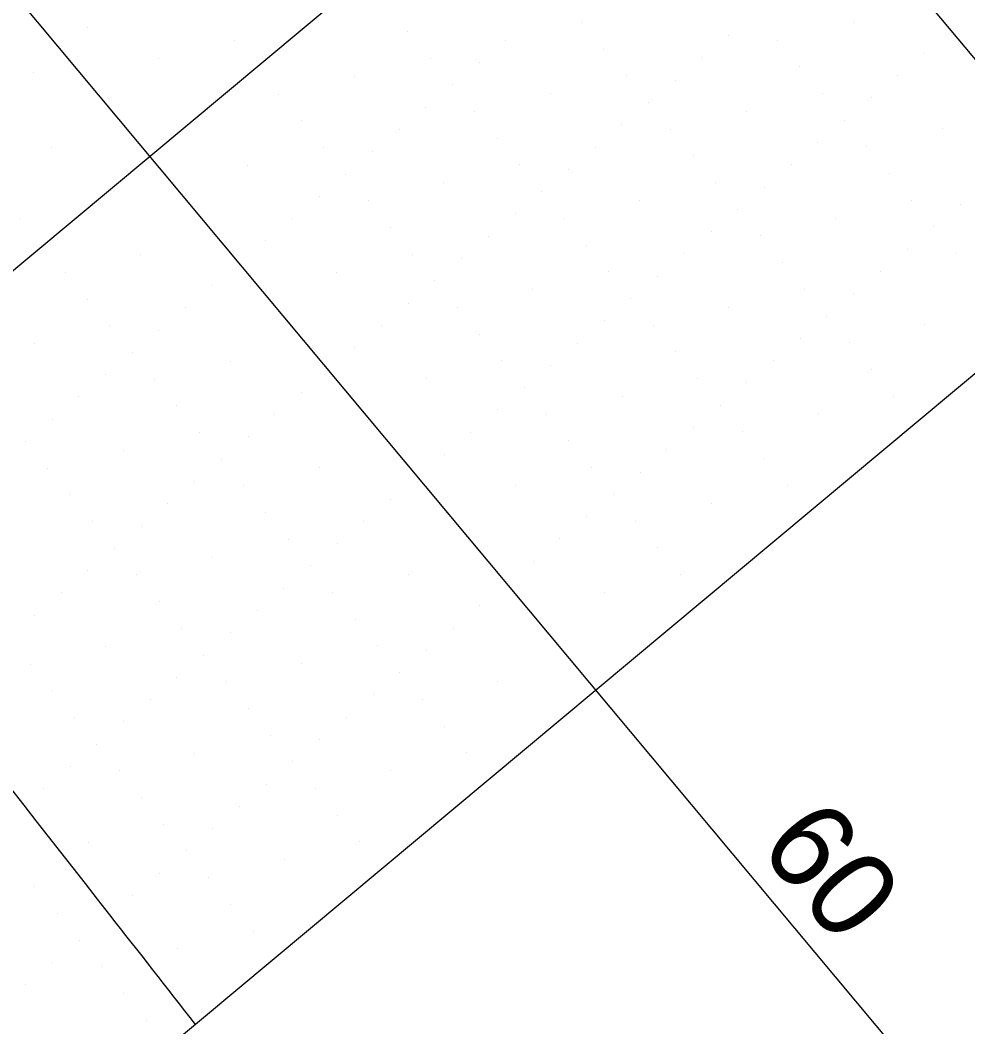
# Model space of a CAD drawing. Extents: x 2042995 to 2043795, y 305365 to 306249.
# Drawn here: x 2043542.18 to 2043569.43, y 305524.47 to 305553.43 of the extents above; entities that cross this region are included whole.
import ezdxf

# ---------------------------------------------------------------- set-up
doc = ezdxf.new("R2010")
doc.units = 0
for name, color, linetype in [('BR_BORDER LINES', 7, 'Continuous'), ('BR_CONCRETE', 7, 'Continuous'), ('BR_GRID DOTS', 7, 'Continuous'), ('BR_GRID LINES', 7, 'Continuous'), ('BR_TEXT', 7, 'Continuous')]:
    doc.layers.add(name, color=color, linetype=linetype)

msp = doc.modelspace()

# ---------------------------------------------------------------- linework, layer by layer
at = {"layer": 'BR_BORDER LINES'}
msp.add_line((2043604.779, 305572.617), (2043493.489, 305479.668), dxfattribs=at)
at = {"layer": 'BR_CONCRETE'}
msp.add_spline([(2043139.109, 306017.548), (2043148.199, 306007.16), (2043160.233, 305993.368), (2043172.245, 305979.557), (2043184.234, 305965.727), (2043196.201, 305951.879), (2043208.145, 305938.012), (2043220.067, 305924.126), (2043231.966, 305910.221), (2043243.843, 305896.297), (2043255.698, 305882.355), (2043267.529, 305868.394), (2043279.339, 305854.414), (2043291.126, 305840.415), (2043302.89, 305826.398), (2043314.632, 305812.361), (2043326.352, 305798.306), (2043338.049, 305784.233), (2043349.724, 305770.14), (2043361.376, 305756.029), (2043373.005, 305741.899), (2043384.613, 305727.75), (2043396.197, 305713.582), (2043407.76, 305699.396), (2043419.299, 305685.191), (2043430.817, 305670.967), (2043442.311, 305656.724), (2043453.784, 305642.463), (2043465.234, 305628.182), (2043476.661, 305613.883), (2043488.066, 305599.566), (2043499.448, 305585.229), (2043510.808, 305570.874), (2043522.146, 305556.5), (2043533.461, 305542.107), (2043544.753, 305527.695), (2043547.219, 305524.543)], degree=3, dxfattribs=at)
at = {"layer": 'BR_GRID DOTS'}
for p, q in [((2043558.323, 305553.361), (2043558.323, 305553.361)), ((2043566.133, 305553.369), (2043566.133, 305553.369)), ((2043544.111, 305553.217), (2043544.111, 305553.217)), ((2043553.33, 305553.099), (2043553.33, 305553.099)), ((2043568.95, 305553.116), (2043568.95, 305553.116)), ((2043548.337, 305552.838), (2043548.337, 305552.838)), ((2043556.147, 305552.846), (2043556.147, 305552.846)), ((2043562.549, 305552.981), (2043562.549, 305552.981)), ((2043563.957, 305552.855), (2043563.957, 305552.855)), ((2043543.344, 305552.576), (2043543.344, 305552.576)), ((2043558.964, 305552.593), (2043558.964, 305552.593)), ((2043568.183, 305552.475), (2043568.183, 305552.475)), ((2043546.161, 305552.323), (2043546.161, 305552.323)), ((2043553.971, 305552.332), (2043553.971, 305552.332)), ((2043555.379, 305552.205), (2043555.379, 305552.205)), ((2043561.781, 305552.34), (2043561.781, 305552.34)), ((2043542.576, 305551.935), (2043542.576, 305551.935)), ((2043564.598, 305552.087), (2043564.598, 305552.087)), ((2043551.795, 305551.817), (2043551.795, 305551.817)), ((2043559.605, 305551.826), (2043559.605, 305551.826)), ((2043561.014, 305551.699), (2043561.014, 305551.699)), ((2043567.415, 305551.834), (2043567.415, 305551.834)), ((2043554.612, 305551.564), (2043554.612, 305551.564)), ((2043565.239, 305551.32), (2043565.239, 305551.32)), ((2043549.619, 305551.303), (2043549.619, 305551.303)), ((2043557.429, 305551.311), (2043557.429, 305551.311)), ((2043560.246, 305551.058), (2043560.246, 305551.058)), ((2043566.648, 305551.193), (2043566.648, 305551.193)), ((2043553.844, 305550.923), (2043553.844, 305550.923)), ((2043555.253, 305550.797), (2043555.253, 305550.797)), ((2043563.063, 305550.805), (2043563.063, 305550.805)), ((2043550.26, 305550.535), (2043550.26, 305550.535)), ((2043565.88, 305550.552), (2043565.88, 305550.552)), ((2043553.077, 305550.282), (2043553.077, 305550.282)), ((2043559.479, 305550.417), (2043559.479, 305550.417)), ((2043560.887, 305550.291), (2043560.887, 305550.291)), ((2043568.697, 305550.299), (2043568.697, 305550.299)), ((2043555.894, 305550.029), (2043555.894, 305550.029)), ((2043565.113, 305549.911), (2043565.113, 305549.911)), ((2043543.091, 305549.759), (2043543.091, 305549.759)), ((2043550.901, 305549.768), (2043550.901, 305549.768)), ((2043552.309, 305549.641), (2043552.309, 305549.641)), ((2043558.711, 305549.776), (2043558.711, 305549.776)), ((2043566.521, 305549.785), (2043566.521, 305549.785)), ((2043561.528, 305549.523), (2043561.528, 305549.523)), ((2043548.725, 305549.253), (2043548.725, 305549.253)), ((2043551.542, 305549), (2043551.542, 305549)), ((2043556.535, 305549.262), (2043556.535, 305549.262)), ((2043557.944, 305549.135), (2043557.944, 305549.135)), ((2043564.345, 305549.27), (2043564.345, 305549.27)), ((2043567.162, 305549.017), (2043567.162, 305549.017)), ((2043554.359, 305548.747), (2043554.359, 305548.747)), ((2043562.169, 305548.756), (2043562.169, 305548.756)), ((2043557.176, 305548.494), (2043557.176, 305548.494)), ((2043563.578, 305548.629), (2043563.578, 305548.629)), ((2043550.774, 305548.359), (2043550.774, 305548.359)), ((2043552.183, 305548.232), (2043552.183, 305548.232)), ((2043559.993, 305548.241), (2043559.993, 305548.241)), ((2043567.803, 305548.25), (2043567.803, 305548.25)), ((2043556.409, 305547.853), (2043556.409, 305547.853)), ((2043562.81, 305547.988), (2043562.81, 305547.988)), ((2043569.212, 305548.123), (2043569.212, 305548.123)), ((2043542.197, 305547.709), (2043542.197, 305547.709)), ((2043550.007, 305547.718), (2043550.007, 305547.718)), ((2043557.817, 305547.727), (2043557.817, 305547.727)), ((2043565.627, 305547.735), (2043565.627, 305547.735)), ((2043552.824, 305547.465), (2043552.824, 305547.465)), ((2043562.043, 305547.347), (2043562.043, 305547.347)), ((2043568.444, 305547.482), (2043568.444, 305547.482)), ((2043549.239, 305547.077), (2043549.239, 305547.077)), ((2043555.641, 305547.212), (2043555.641, 305547.212)), ((2043563.451, 305547.221), (2043563.451, 305547.221)), ((2043545.655, 305546.689), (2043545.655, 305546.689)), ((2043553.465, 305546.697), (2043553.465, 305546.697)), ((2043558.458, 305546.959), (2043558.458, 305546.959)), ((2043561.275, 305546.706), (2043561.275, 305546.706)), ((2043567.677, 305546.841), (2043567.677, 305546.841)), ((2043569.085, 305546.715), (2043569.085, 305546.715)), ((2043548.472, 305546.436), (2043548.472, 305546.436)), ((2043554.874, 305546.571), (2043554.874, 305546.571)), ((2043564.092, 305546.453), (2043564.092, 305546.453)), ((2043543.479, 305546.174), (2043543.479, 305546.174)), ((2043551.289, 305546.183), (2043551.289, 305546.183)), ((2043559.099, 305546.191), (2043559.099, 305546.191)), ((2043566.909, 305546.2), (2043566.909, 305546.2)), ((2043554.106, 305545.93), (2043554.106, 305545.93)), ((2043560.508, 305546.065), (2043560.508, 305546.065)), ((2043547.704, 305545.795), (2043547.704, 305545.795)), ((2043556.923, 305545.677), (2043556.923, 305545.677)), ((2043564.733, 305545.686), (2043564.733, 305545.686)), ((2043566.142, 305545.559), (2043566.142, 305545.559)), ((2043544.12, 305545.407), (2043544.12, 305545.407)), ((2043553.338, 305545.289), (2043553.338, 305545.289)), ((2043559.74, 305545.424), (2043559.74, 305545.424)), ((2043546.937, 305545.154), (2043546.937, 305545.154)), ((2043554.747, 305545.162), (2043554.747, 305545.162)), ((2043562.557, 305545.171), (2043562.557, 305545.171)), ((2043558.973, 305544.783), (2043558.973, 305544.783)), ((2043560.381, 305544.656), (2043560.381, 305544.656)), ((2043565.374, 305544.918), (2043565.374, 305544.918)), ((2043568.191, 305544.665), (2043568.191, 305544.665)), ((2043544.761, 305544.639), (2043544.761, 305544.639)), ((2043546.169, 305544.513), (2043546.169, 305544.513)), ((2043552.571, 305544.648), (2043552.571, 305544.648)), ((2043555.388, 305544.395), (2043555.388, 305544.395)), ((2043542.585, 305544.125), (2043542.585, 305544.125)), ((2043558.205, 305544.142), (2043558.205, 305544.142)), ((2043564.607, 305544.277), (2043564.607, 305544.277)), ((2043566.015, 305544.15), (2043566.015, 305544.15)), ((2043545.402, 305543.872), (2043545.402, 305543.872)), ((2043551.803, 305544.007), (2043551.803, 305544.007)), ((2043561.022, 305543.889), (2043561.022, 305543.889)), ((2043548.219, 305543.619), (2043548.219, 305543.619)), ((2043556.029, 305543.627), (2043556.029, 305543.627)), ((2043557.438, 305543.501), (2043557.438, 305543.501)), ((2043563.839, 305543.636), (2043563.839, 305543.636)), ((2043544.634, 305543.231), (2043544.634, 305543.231)), ((2043551.036, 305543.366), (2043551.036, 305543.366)), ((2043566.656, 305543.383), (2043566.656, 305543.383)), ((2043546.043, 305543.104), (2043546.043, 305543.104)), ((2043553.853, 305543.113), (2043553.853, 305543.113)), ((2043561.663, 305543.121), (2043561.663, 305543.121)), ((2043563.072, 305542.995), (2043563.072, 305542.995)), ((2043550.268, 305542.725), (2043550.268, 305542.725)), ((2043556.67, 305542.86), (2043556.67, 305542.86)), ((2043543.867, 305542.59), (2043543.867, 305542.59)), ((2043559.487, 305542.607), (2043559.487, 305542.607)), ((2043562.304, 305542.354), (2043562.304, 305542.354)), ((2043567.297, 305542.615), (2043567.297, 305542.615)), ((2043546.684, 305542.337), (2043546.684, 305542.337)), ((2043549.501, 305542.084), (2043549.501, 305542.084)), ((2043555.903, 305542.219), (2043555.903, 305542.219)), ((2043557.311, 305542.092), (2043557.311, 305542.092)), ((2043565.121, 305542.101), (2043565.121, 305542.101)), ((2043543.099, 305541.949), (2043543.099, 305541.949)), ((2043547.325, 305541.569), (2043547.325, 305541.569)), ((2043555.135, 305541.578), (2043555.135, 305541.578)), ((2043561.537, 305541.713), (2043561.537, 305541.713)), ((2043562.945, 305541.586), (2043562.945, 305541.586)), ((2043542.332, 305541.308), (2043542.332, 305541.308)), ((2043548.733, 305541.443), (2043548.733, 305541.443)), ((2043557.952, 305541.325), (2043557.952, 305541.325)), ((2043545.149, 305541.055), (2043545.149, 305541.055)), ((2043554.368, 305540.937), (2043554.368, 305540.937)), ((2043560.769, 305541.072), (2043560.769, 305541.072)), ((2043547.966, 305540.802), (2043547.966, 305540.802)), ((2043563.586, 305540.819), (2043563.586, 305540.819)), ((2043542.973, 305540.54), (2043542.973, 305540.54)), ((2043550.783, 305540.549), (2043550.783, 305540.549)), ((2043558.593, 305540.557), (2043558.593, 305540.557)), ((2043560.002, 305540.431), (2043560.002, 305540.431)), ((2043547.198, 305540.161), (2043547.198, 305540.161)), ((2043548.607, 305540.034), (2043548.607, 305540.034)), ((2043553.6, 305540.296), (2043553.6, 305540.296)), ((2043556.417, 305540.043), (2043556.417, 305540.043)), ((2043564.227, 305540.051), (2043564.227, 305540.051)), ((2043543.614, 305539.773), (2043543.614, 305539.773)), ((2043559.234, 305539.79), (2043559.234, 305539.79)), ((2043546.431, 305539.52), (2043546.431, 305539.52)), ((2043552.833, 305539.655), (2043552.833, 305539.655)), ((2043562.051, 305539.537), (2043562.051, 305539.537)), ((2043549.248, 305539.267), (2043549.248, 305539.267)), ((2043544.255, 305539.005), (2043544.255, 305539.005)), ((2043545.663, 305538.879), (2043545.663, 305538.879)), ((2043552.065, 305539.014), (2043552.065, 305539.014)), ((2043558.467, 305539.149), (2043558.467, 305539.149)), ((2043559.875, 305539.022), (2043559.875, 305539.022)), ((2043549.889, 305538.499), (2043549.889, 305538.499)), ((2043551.297, 305538.373), (2043551.297, 305538.373)), ((2043557.699, 305538.508), (2043557.699, 305538.508)), ((2043544.896, 305538.238), (2043544.896, 305538.238)), ((2043560.516, 305538.255), (2043560.516, 305538.255)), ((2043547.713, 305537.985), (2043547.713, 305537.985)), ((2043550.53, 305537.732), (2043550.53, 305537.732)), ((2043556.932, 305537.867), (2043556.932, 305537.867)), ((2043544.128, 305537.597), (2043544.128, 305537.597)), ((2043545.537, 305537.47), (2043545.537, 305537.47)), ((2043553.347, 305537.479), (2043553.347, 305537.479)), ((2043561.157, 305537.487), (2043561.157, 305537.487)), ((2043556.164, 305537.226), (2043556.164, 305537.226)), ((2043543.361, 305536.956), (2043543.361, 305536.956)), ((2043549.762, 305537.091), (2043549.762, 305537.091)), ((2043551.171, 305536.964), (2043551.171, 305536.964)), ((2043558.981, 305536.973), (2043558.981, 305536.973)), ((2043546.178, 305536.703), (2043546.178, 305536.703)), ((2043555.397, 305536.585), (2043555.397, 305536.585)), ((2043542.593, 305536.315), (2043542.593, 305536.315)), ((2043548.995, 305536.45), (2043548.995, 305536.45)), ((2043551.812, 305536.197), (2043551.812, 305536.197)), ((2043546.819, 305535.935), (2043546.819, 305535.935)), ((2043548.227, 305535.809), (2043548.227, 305535.809)), ((2043554.629, 305535.944), (2043554.629, 305535.944)), ((2043544.643, 305535.421), (2043544.643, 305535.421)), ((2043552.453, 305535.429), (2043552.453, 305535.429)), ((2043547.46, 305535.168), (2043547.46, 305535.168)), ((2043553.862, 305535.303), (2043553.862, 305535.303)), ((2043542.467, 305534.906), (2043542.467, 305534.906)), ((2043550.277, 305534.915), (2043550.277, 305534.915)), ((2043546.692, 305534.527), (2043546.692, 305534.527)), ((2043553.094, 305534.662), (2043553.094, 305534.662)), ((2043548.101, 305534.4), (2043548.101, 305534.4)), ((2043555.911, 305534.409), (2043555.911, 305534.409)), ((2043543.108, 305534.138), (2043543.108, 305534.138)), ((2043552.327, 305534.021), (2043552.327, 305534.021)), ((2043545.925, 305533.885), (2043545.925, 305533.885)), ((2043553.735, 305533.894), (2043553.735, 305533.894)), ((2043543.749, 305533.371), (2043543.749, 305533.371)), ((2043548.742, 305533.633), (2043548.742, 305533.633)), ((2043551.559, 305533.38), (2043551.559, 305533.38)), ((2043545.157, 305533.244), (2043545.157, 305533.244)), ((2043554.376, 305533.127), (2043554.376, 305533.127)), ((2043549.383, 305532.865), (2043549.383, 305532.865)), ((2043544.39, 305532.603), (2043544.39, 305532.603)), ((2043550.791, 305532.738), (2043550.791, 305532.738)), ((2043547.207, 305532.35), (2043547.207, 305532.35)), ((2043555.017, 305532.359), (2043555.017, 305532.359)), ((2043543.622, 305531.962), (2043543.622, 305531.962)), ((2043550.024, 305532.097), (2043550.024, 305532.097)), ((2043545.031, 305531.836), (2043545.031, 305531.836)), ((2043552.841, 305531.844), (2043552.841, 305531.844)), ((2043549.256, 305531.456), (2043549.256, 305531.456)), ((2043542.855, 305531.321), (2043542.855, 305531.321)), ((2043545.672, 305531.068), (2043545.672, 305531.068)), ((2043550.665, 305531.33), (2043550.665, 305531.33)), ((2043548.489, 305530.815), (2043548.489, 305530.815)), ((2043551.306, 305530.562), (2043551.306, 305530.562)), ((2043546.313, 305530.301), (2043546.313, 305530.301)), ((2043547.721, 305530.174), (2043547.721, 305530.174)), ((2043544.137, 305529.786), (2043544.137, 305529.786)), ((2043551.947, 305529.795), (2043551.947, 305529.795)), ((2043546.954, 305529.533), (2043546.954, 305529.533)), ((2043549.771, 305529.28), (2043549.771, 305529.28)), ((2043546.186, 305528.892), (2043546.186, 305528.892)), ((2043547.595, 305528.766), (2043547.595, 305528.766)), ((2043542.602, 305528.504), (2043542.602, 305528.504)), ((2043545.419, 305528.251), (2043545.419, 305528.251)), ((2043548.236, 305527.998), (2043548.236, 305527.998)), ((2043543.243, 305527.737), (2043543.243, 305527.737)), ((2043544.651, 305527.61), (2043544.651, 305527.61)), ((2043548.877, 305527.231), (2043548.877, 305527.231)), ((2043543.884, 305526.969), (2043543.884, 305526.969)), ((2043546.701, 305526.716), (2043546.701, 305526.716)), ((2043543.116, 305526.328), (2043543.116, 305526.328)), ((2043544.525, 305526.202), (2043544.525, 305526.202)), ((2043542.349, 305525.687), (2043542.349, 305525.687)), ((2043545.166, 305525.434), (2043545.166, 305525.434)), ((2043545.807, 305524.667), (2043545.807, 305524.667))]:
    msp.add_line(p, q, dxfattribs=at)
at = {"layer": 'BR_GRID LINES'}
for p, q in [((2043153.138, 306050.98), (2043584.762, 305534.185)), ((2043137.788, 306038.16), (2043569.411, 305521.364)), ((2043591.959, 305587.968), (2043484.506, 305498.224))]:
    msp.add_line(p, q, dxfattribs=at)

# ---------------------------------------------------------------- texts
at = {"layer": 'BR_TEXT'}
msp.add_text('60', height=2.5, rotation=309.8684, dxfattribs=at).set_placement((2043563.362, 305529.622))

doc.saveas('drawing.dxf')
